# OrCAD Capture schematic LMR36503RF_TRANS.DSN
size D; title: LMR36503RF, 3 V–65 V, 0.3-A Ultra-Small Synchronous; rev: 1.0; note: Datasheet: SNVSBB4          EVM: SNVU672
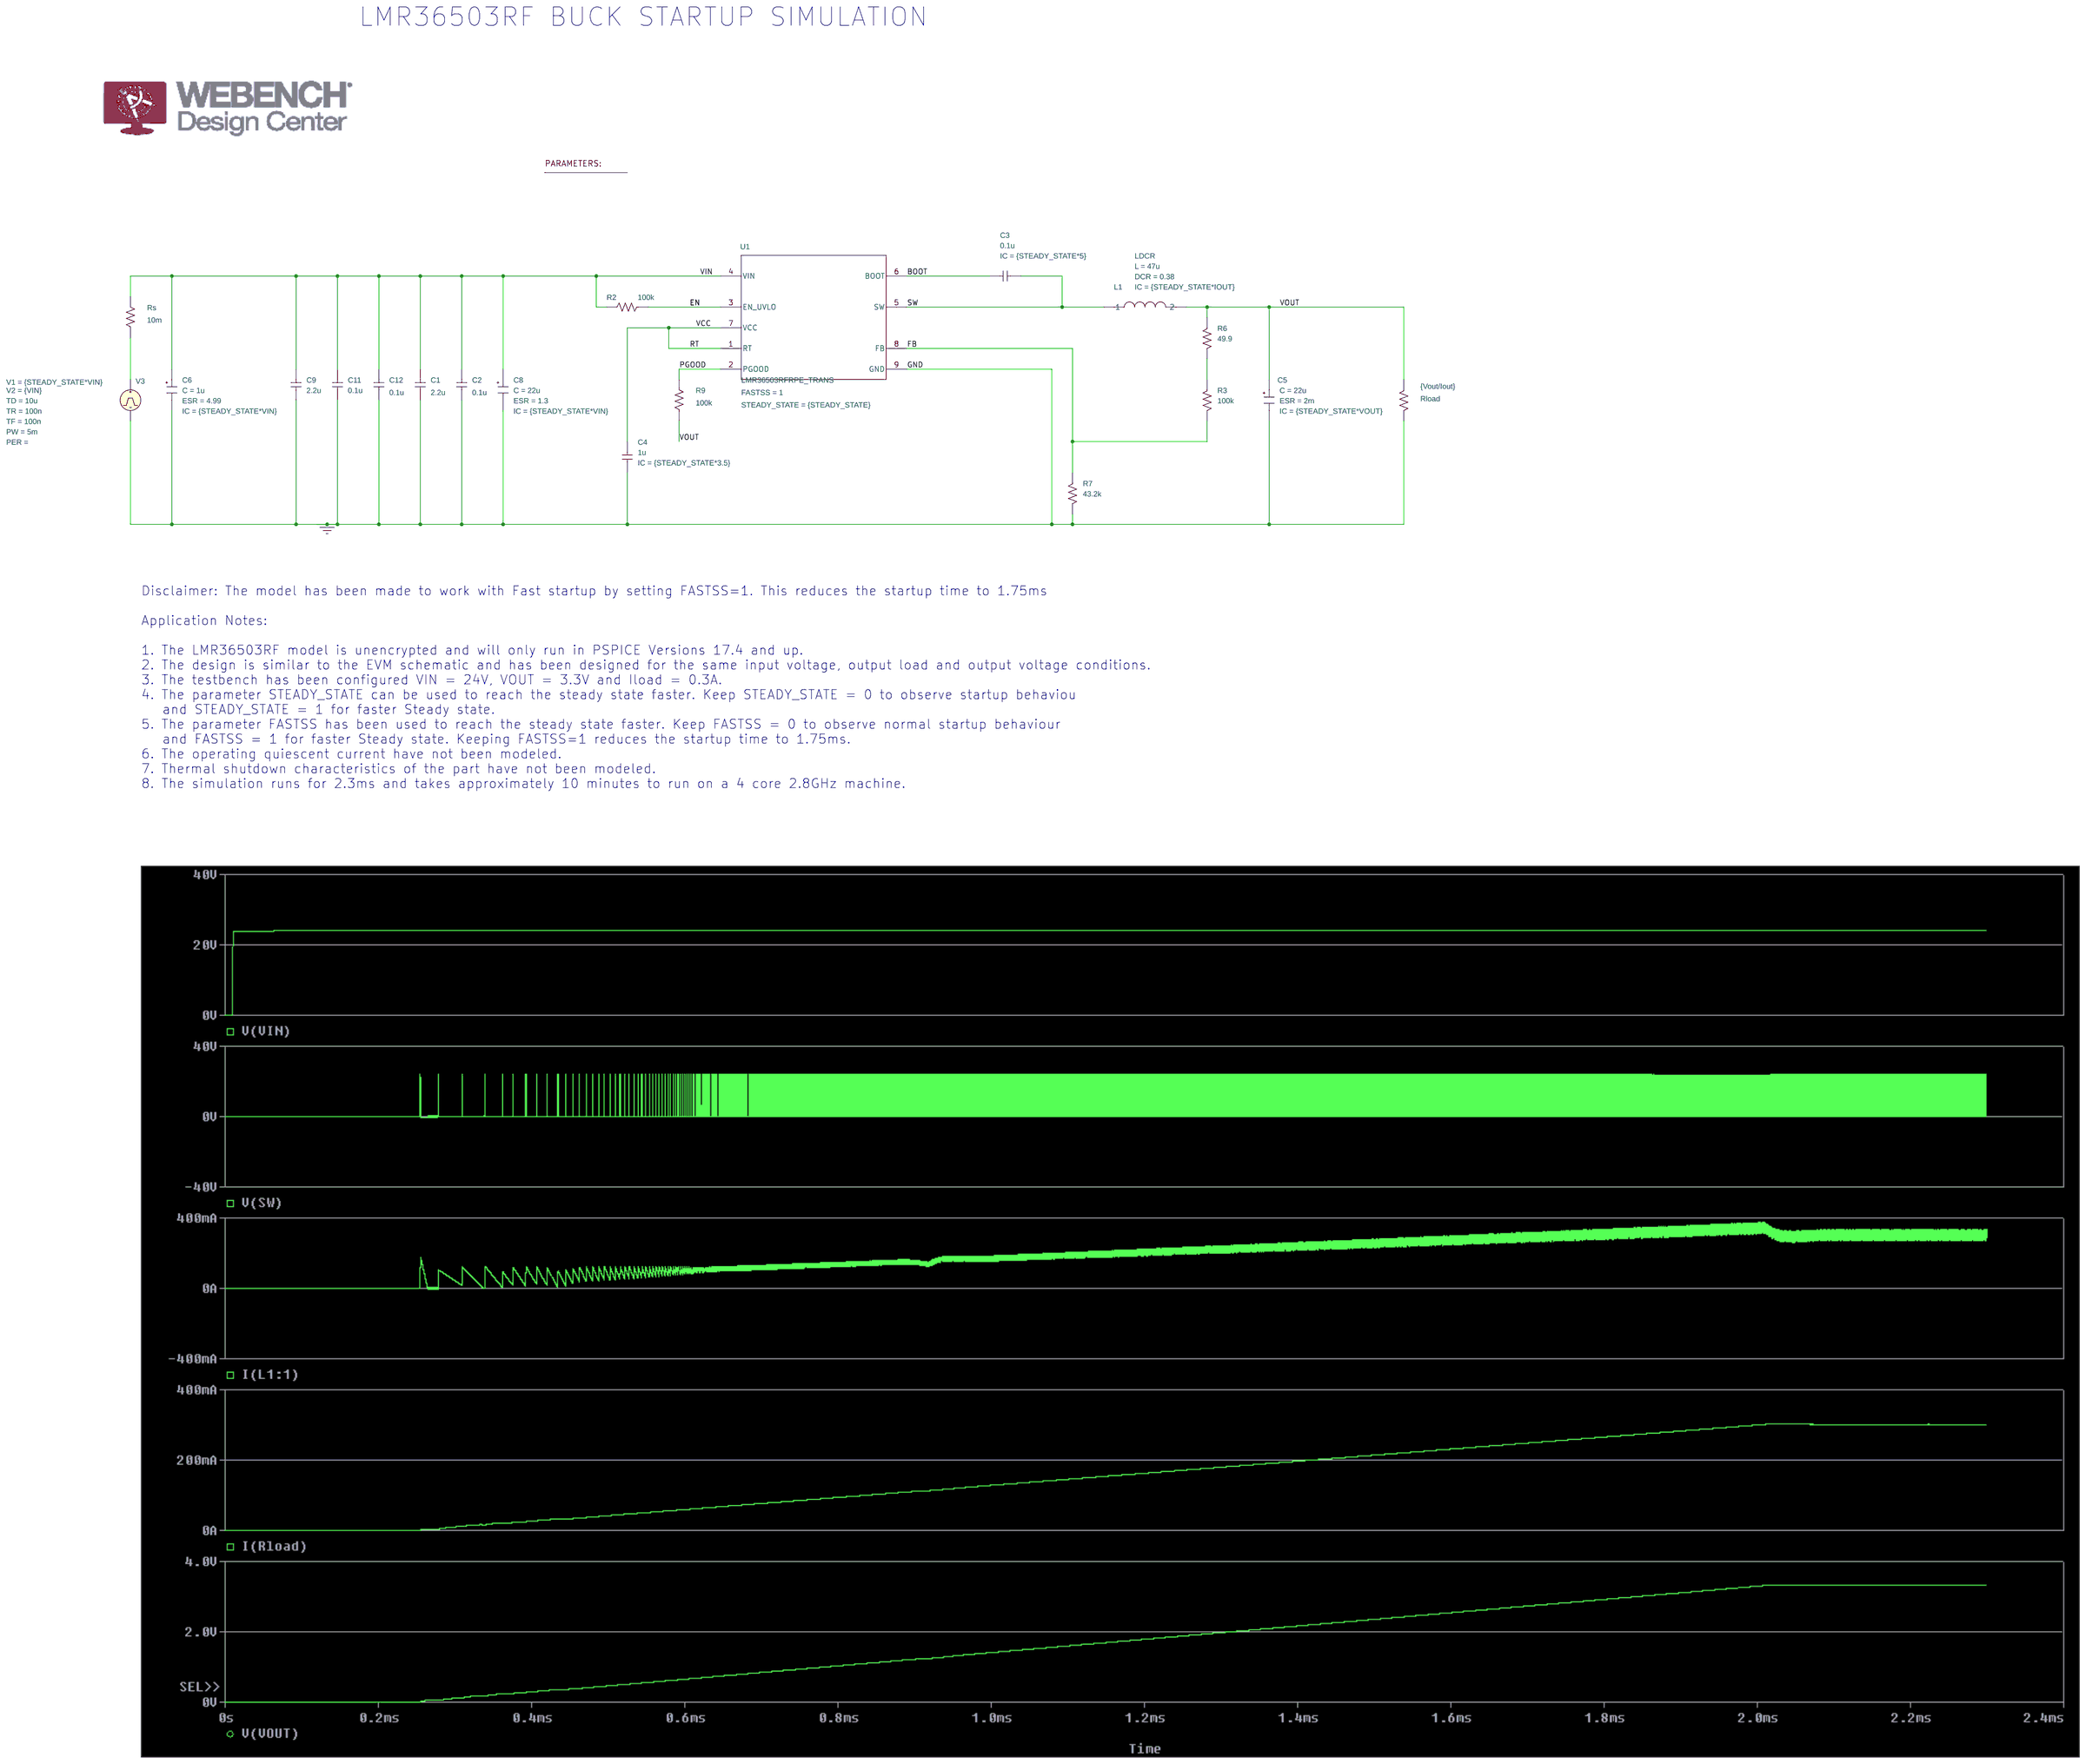
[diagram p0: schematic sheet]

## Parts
5  PARAM
C1  2.2u  [RAD/CK05]
C2  0.1u  [RAD/CK05]
C3  0.1u  [CK05]
C4  1u  [RAD/CK05]
C5  CESR
C6  CESR
C8  CESR
C9  2.2u  [RAD/CK05]
C11  0.1u  [RAD/CK05]
C12  0.1u  [RAD/CK05]
L1  LDCR
R2  100k  [AX/RC05]
R3  100k  [AX/RC05]
R6  49.9  [AX/RC05]
R7  43.2k  [AX/RC05]
R9  100k  [RC05]
Rload  {Vout/Iout}  [AX/RC05]
Rs  10m  [AX/RC05]
U1  LMR36503RFRPE_TRANS  [RPE0009A]
V3  VPULSE

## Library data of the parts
5 = PARAM: IOUT: 0.3; STEADY_STATE: 0; VIN: 24; vout: 3.3
C1 C2 C9 C11 C12 = C
C3 = C: IC: {STEADY_STATE*5}
C4 = C: IC: {STEADY_STATE*3.5}
C5 = CESR_0: C: 22u; ESR: 2m; IC: {STEADY_STATE*VOUT}; PSpiceTemplate: X^@REFDES %IN %OUT @MODEL PARAMS:  ?C|C=@C||C=100u|  ?ESR|ESR=@ESR||ESR=0.01| ?X|X=@X||X=2|  ?IC|IC=@IC||IC=2|; X: 1
C6 = CESR_0: C: 1u; ESR: 4.99; IC: {STEADY_STATE*VIN}; PSpiceTemplate: X^@REFDES %IN %OUT @MODEL PARAMS:  ?C|C=@C||C=100u|  ?ESR|ESR=@ESR||ESR=0.01| ?X|X=@X||X=2|  ?IC|IC=@IC||IC=2|; X: 1
C8 = CESR_0: C: 22u; ESR: 1.3; IC: {STEADY_STATE*VIN}; PSpiceTemplate: X^@REFDES %IN %OUT @MODEL PARAMS:  ?C|C=@C||C=100u|  ?ESR|ESR=@ESR||ESR=0.01| ?X|X=@X||X=2|  ?IC|IC=@IC||IC=2|; X: 1
L1 = LDCR: DCR: 0.38; IC: {STEADY_STATE*IOUT}; L: 47u; PSpiceTemplate: X^@REFDES %1 %2 @MODEL PARAMS: ?L|L=@L||L=10U| ?DCR|DCR=@DCR||DCR=20M| ?IC|IC=@IC||IC=0|
R2 R3 R6 R7 R9 Rload Rs = R
U1 = LMR36503RFRPE_TRANS: FASTSS: 1; STEADY_STATE: {STEADY_STATE}
V3 = VPULSE: PW: 5m; TD: 10u; TF: 100n; TR: 100n; V1: {STEADY_STATE*VIN}; V2: {VIN}

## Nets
VIN: C1.2 C2.2 C6.1(IN) C8.1(IN) C9.2 C11.2 C12.2 R2.2 Rs.2 U1.4(VIN)
0: C1.1 C2.1 C4.2 C5.2(OUT) C6.2(OUT) C8.2(OUT) C9.1 C11.1 C12.1 R7.2 Rload.2 U1.9(GND) V3.2(-)
BOOT: C3.1 U1.6(BOOT)
EN: R2.1 U1.3(EN_UVLO)
FB: R3.2 R7.1 U1.8(FB)
PGOOD: R9.2 U1.2(PGOOD)
RT: C4.1 U1.1(RT) U1.7(VCC)
SW: C3.2 L1.1 U1.5(SW)
VOUT: C5.1(IN) L1.2 R6.1 R9.1 Rload.1
N17847: Rs.1 V3.1(+)
N18233: R3.1 R6.2

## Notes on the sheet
- LMR36503RF BUCK STARTUP SIMULATION
- Disclaimer: The model has been made to work with Fast startup by setting FASTSS=1. This reduces the startup time to 1.75ms
  Application Notes:
  1. The LMR36503RF model is unencrypted and will only run in PSPICE Versions 17.4 and up.
  2. The design is similar to the EVM schematic and has been designed for the same input voltage, output load and output voltage conditions.
  3. The testbench has been configured VIN = 24V, VOUT = 3.3V and Iload = 0.3A.
  4. The parameter STEADY_STATE can be used to reach the steady state faster. Keep STEADY_STATE = 0 to observe startup behaviou
     and STEADY_STATE = 1 for faster Steady state.
  5. The parameter FASTSS has been used to reach the steady state faster. Keep FASTSS = 0 to observe normal startup behaviour
     and FASTSS = 1 for faster Steady state. Keeping FASTSS=1 reduces the startup time to 1.75ms.
  6. The operating quiescent current have not been modeled.
  7. Thermal shutdown characteristics of the part have not been modeled.
  8. The simulation runs for 2.3ms and takes approximately 10 minutes to run on a 4 core 2.8GHz machine.
